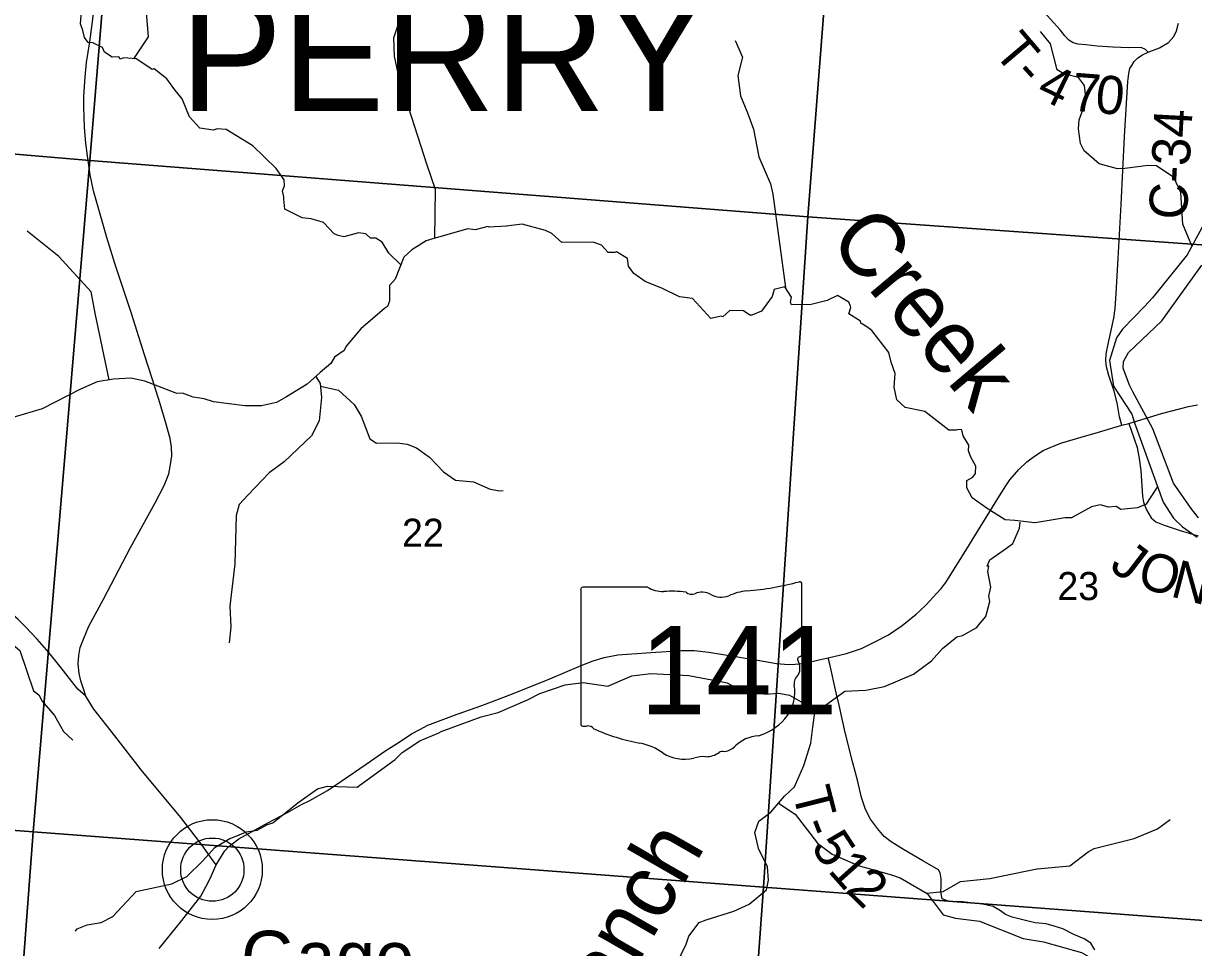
# Model space of a CAD drawing. Extents: x 1878108 to 2183446, y 146837 to 508383.
# Drawn here: x 1996150 to 2005354, y 289361 to 296632 of the extents above; entities that cross this region are included whole.
import ezdxf

# ---------------------------------------------------------------- set-up
doc = ezdxf.new("R2010")
doc.units = 0
for name, color, linetype in [('GM_X_County_Road', 7, 'Continuous'), ('GM_X_County_Road_Text', 7, 'Continuous'), ('GM_X_Major_River', 7, 'Continuous'), ('GM_X_Minor_River', 7, 'Continuous'), ('GM_X_Minor_River_Text', 7, 'Continuous'), ('GM_X_Section', 7, 'Continuous'), ('GM_X_Section_Text', 7, 'Continuous'), ('GM_X_State_Location', 7, 'Continuous'), ('GM_X_State_Route', 7, 'Continuous'), ('GM_X_State_Shield', 7, 'Continuous'), ('GM_X_Township_Road', 7, 'Continuous'), ('GM_X_Township_Road_Text', 7, 'Continuous'), ('GM_X_Township_ROW', 7, 'Continuous'), ('GM_X_Township_Text', 7, 'Continuous'), ('GM_X_Unincorporated', 7, 'Continuous'), ('GM_X_Unincorporated_Location', 7, 'Continuous'), ('GM_X_Unincorporated_Text', 7, 'Continuous')]:
    doc.layers.add(name, color=color, linetype=linetype)

msp = doc.modelspace()

# ---------------------------------------------------------------- linework, layer by layer
at = {"layer": 'GM_X_County_Road'}
for points in [[(2004789, 293470.2), (2004772.2, 293536.3), (2004753, 293648.1), (2004730.1, 293738.3), (2004688, 293862.1), (2004668.8, 293929.4), (2004664, 293978.7), (2004666.4, 294031.6), (2004685.6, 294121.8), (2004726.5, 294314.1), (2004737.3, 294388.7), (2004745.7, 294507.7), (2004760.2, 294783), (2004784.2, 295208.6), (2004811.9, 295743.6), (2004835.9, 296174.1), (2004844.3, 296239), (2004852.7, 296277.5), (2004867.2, 296301.5), (2004887.6, 296332.8), (2004916.5, 296361.6), (2004951.3, 296384.5), (2004997, 296406.1), (2005085.5, 296440.9), (2005157.1, 296482.7), (2005198.8, 296528), (2005220.3, 296573.3), (2005234.6, 296632.9)], [(2004845.5, 293484.6), (2004862.4, 293430.5), (2004909.3, 293294.6), (2004926.1, 293209.3), (2004939.3, 293115.5), (2004952.2, 292913.4), (2004959.8, 292864.1), (2004983.8, 292804.7), (2005020.5, 292741.5), (2005057.1, 292711.2), (2005122.9, 292683.3), (2005249.3, 292642.9), (2005389.6, 292601.2)], [(1996641.8, 291338.4), (1996579.3, 291394.9), (1996436.6, 291574.8), (1996348.9, 291683.3), (1996259.7, 291787.3), (1996167.5, 291885.5), (1996105.1, 291944.9), (1996017.4, 292020.7), (1995889.5, 292127.8), (1995666.5, 292294.3), (1995559.5, 292365.6), (1995456.9, 292423.6), (1995199.8, 292566.3), (1995091.2, 292634.7), (1995063, 292664.4), (1995031.8, 292707.5), (1994993.1, 292802.7), (1994960.4, 292896.3), (1994915.8, 292975.1), (1994884.6, 293013.7)]]:
    msp.add_lwpolyline(points, dxfattribs=at)
at = {"layer": 'GM_X_Major_River'}
for points in [[(2005521.3, 295211.9), (2005304.4, 294812.4), (2005031.4, 294472.9), (2004967.6, 294404.5), (2004794, 294227.6), (2004748.2, 294157.3), (2004692.7, 293980.8), (2004723.3, 293778.6), (2004868, 293558.8), (2004890.2, 293490.8), (2005116, 292866.5), (2005196.4, 292740.6), (2005266.6, 292670.7), (2005382.8, 292591)], [(2005392.4, 292743.3), (2005334.2, 292815.2), (2005195.6, 293015.1), (2005034.3, 293441.2), (2004875.5, 293733.1), (2004849.3, 293787.1), (2004798.9, 293919.1), (2004802.8, 293971.2), (2004842.6, 294043.5), (2005103.9, 294292.8), (2005418.7, 294730.7)]]:
    msp.add_lwpolyline(points, dxfattribs=at)
at = {"layer": 'GM_X_Minor_River'}
for points in [[(1997019, 296353.4), (1997134.7, 296527.8), (1997119.5, 296717.8), (1997097.4, 296805.8), (1996997.1, 297041.8), (1996976.5, 297210.1), (1996933.5, 297345.8), (1996927.1, 297517.1), (1997068.5, 297968), (1997046.2, 298023.8), (1996954.2, 298088.4), (1996898.3, 298152.5), (1996822.2, 298332.6), (1996746.5, 298577.1), (1996696.1, 298691.1)], [(1999387.5, 294943.5), (1999392.6, 295324.3), (1999325.5, 295517.9), (1999105, 296200.5), (1999068.6, 296373.9), (1999064.5, 296518.9), (1999118, 296684.2), (1999215.8, 296822.3), (1999453.7, 297158), (1999598.9, 297254.6), (1999628.7, 297278.8), (1999773.4, 297309.1), (1999947.8, 297391.7), (2000213.7, 297343.4), (2000342.5, 297318.6), (2000496.7, 297340.2), (2000525.2, 297374.5), (2000757.7, 297427), (2000888.3, 297398), (2000974.2, 297420.3), (2001003.2, 297432.4), (2001060, 297470.8), (2001208.8, 297677.8)], [(1999119.7, 294731.6), (1999025.2, 294823.9), (1998972.9, 294909.8), (1998922.8, 294941.8), (1998880.7, 294943.7), (1998842.6, 294975.6), (1998786.5, 294983.5), (1998670.5, 294953.3), (1998626.5, 294963.2), (1998594.4, 294977.1), (1998510.1, 295067), (1998413.9, 295094.8), (1998341.9, 295102.7), (1998207.6, 295170.4), (1998197.3, 295250.4), (1998199.3, 295266.4), (1998189.2, 295314.4), (1998205.1, 295354.4), (1998200.9, 295400.4), (1998138.6, 295490.3), (1997954, 295669.9), (1997745.5, 295797.5), (1997673.4, 295803.4), (1997643.4, 295793.4), (1997537.3, 295807.2), (1997457, 295897), (1997398.5, 296038.9), (1997342.3, 296108.8), (1997278, 296196.7), (1997177.7, 296274.5), (1997163.7, 296270.5), (1997153.7, 296278.4), (1997037.4, 296352.2), (1996939.3, 296362), (1996911.3, 296352), (1996901.2, 296368), (1996847.2, 296365.9), (1996789, 296405.8), (1996772.9, 296441.7), (1996696.8, 296479.6), (1996660.7, 296481.5), (1996630.6, 296521.5), (1996618.4, 296575.5), (1996600.3, 296629.4), (1996615.7, 296829.4)], [(2005339.8, 294881.9), (2005270.5, 295052.1), (2005254, 295301.1), (2005199.5, 295420.2), (2005062.4, 295510.4), (2004996.3, 295515.3), (2004813.4, 295489.7), (2004755.2, 295488.5), (2004611.4, 295526.6), (2004494.5, 295630.5), (2004465.2, 295687.1), (2004448.8, 295801.6), (2004453.8, 295873.8), (2004510.1, 296023.5), (2004495.8, 296144), (2004448.5, 296206.9), (2004396.5, 296219.6), (2004332.6, 296236.5), (2004280.9, 296267.3), (2004227.6, 296470.7), (2004148.8, 296568.1)], [(2001748.9, 296498.9), (2001806.1, 296366.3), (2001770.1, 296222), (2001791.3, 296061.7), (2001846.5, 295929.2), (2001893.9, 295799.3), (2001933.3, 295583.5), (2002027.2, 295370), (2002045.7, 295288.3), (2002143.5, 294554.7)], [(1996825.2, 293828.4), (1996717.7, 294338.3), (1996681.9, 294519.7), (1996429.8, 294798.3), (1996180.3, 294998.2)], [(1999704.2, 295008.9), (1999645.1, 295015), (1999377.1, 294940.6), (1999317.1, 294922.5), (1999205.2, 294850.3), (1999141.3, 294792.1), (1999073.8, 294620), (1999029.9, 294570), (1999030.2, 294448), (1999014.3, 294404), (1998990.4, 294389.9), (1998803.3, 294228.1)], [(1999950.4, 295036.5), (1999813.2, 295029.3), (1999803.2, 295035.3), (1999704.2, 295008.9)], [(2000902, 294782.2), (2000814.5, 294835.2), (2000798.5, 294829.1), (2000748.5, 294829), (2000698.3, 294887), (2000632.2, 294910.8), (2000384, 294908.4), (2000305.7, 294980.2), (2000255.6, 295002.1), (2000073.4, 295051.8), (1999947.1, 295036.4)], [(2004107.5, 292701.9), (2004105, 292703.2), (2003946.9, 292721), (2003872.8, 292726.8), (2003730.4, 292816.6), (2003612.1, 292900.3), (2003569.9, 292978.3), (2003571.7, 293036.3), (2003617.6, 293062.3), (2003637.6, 293090.4), (2003641.4, 293148.4), (2003603.2, 293220.3), (2003583, 293268.3), (2003586.9, 293314.3), (2003540.7, 293386.2), (2003530.5, 293434.2), (2003504.5, 293438.1), (2003486.5, 293432.1), (2003428.5, 293432), (2003239.9, 293579.6), (2003085.7, 293611.4), (2003019.5, 293671.2), (2002999.2, 293771.2), (2003006.9, 293877.2), (2002974.6, 293967.1), (2002958.4, 294043.1), (2002823.8, 294214.8), (2002783.7, 294244.8), (2002735.6, 294274.7), (2002735.5, 294290.7), (2002643.3, 294346.5), (2002657.2, 294396.5), (2002655.2, 294408.5), (2002643.1, 294438.5), (2002552.8, 294492.3), (2002472.9, 294452.2), (2002334.9, 294417.9), (2002214.8, 294419.7), (2002192.8, 294417.7), (2002182.7, 294439.7), (2002192.6, 294477.7), (2002140.3, 294559.6), (2002054.3, 294539.4), (2002040.5, 294483.4), (2001954.7, 294369.3), (2001880.8, 294337.1), (2001862.7, 294337.1), (2001814.6, 294371), (2001706.5, 294372.8), (2001650.6, 294322.7), (2001638.6, 294328.7), (2001556.6, 294310.5), (2001414, 294468.3), (2001311.9, 294480.1), (2001177.6, 294545.8), (2001041.4, 294601.6), (2000951.1, 294663.4), (2000908.9, 294721.3), (2000902, 294782.2)], [(1998803.3, 294228.1), (1998688.9, 294091.4), (1998673, 294059.4), (1998597.1, 294005.2), (1998569.2, 293955.2), (1998483.4, 293885), (1998381.5, 293794.9), (1998219.7, 293694.6), (1998139.7, 293648.4), (1998023.7, 293624.2)], [(1998023.7, 293624.2), (1997891.6, 293622), (1997645.3, 293653.5), (1997573.2, 293679.4), (1997485.1, 293691.2), (1997401, 293723.1), (1997356.9, 293721), (1997342.9, 293725), (1997104.5, 293816.5), (1996996.3, 293840.3), (1996858.2, 293834.1), (1996730.2, 293811.9), (1996600.3, 293755.6), (1996298.5, 293599.1), (1996014.5, 293514.6)], [(1998449.4, 293855), (1998484.6, 293797.7), (1998495.2, 293688.4), (1998476.6, 293504.7), (1998416.3, 293386.1), (1998201.4, 293181.6), (1998083.2, 293097.1), (1997918.6, 292923.4), (1997847.1, 292847.8), (1997823.1, 292761), (1997813.1, 292379.6), (1997774.3, 292046.5), (1997781.3, 291885.1), (1997768.5, 291757.3)], [(1998486.7, 293776.9), (1998627.7, 293745.7), (1998752.6, 293632.7), (1998806.7, 293542.5), (1998874.9, 293364.9), (1998926.7, 293329.2), (1999089.6, 293332.2), (1999169.3, 293322.8), (1999241.6, 293293.7), (1999344.9, 293218.3), (1999455.6, 293104.2), (1999549.5, 293037.5), (1999689.3, 293025.9), (1999821.9, 292966.6), (1999897.3, 292953.5), (1999923.7, 292957.7)], [(2005071.7, 292990.1), (2005002.2, 292882.6), (2004980.6, 292850.3), (2004912.8, 292821.7), (2004780.7, 292808.5), (2004746.3, 292830.2), (2004684.2, 292825.7), (2004619.9, 292843.1), (2004551.9, 292828.5), (2004392.7, 292742.9), (2004344.6, 292742.5), (2004107.5, 292701.9)], [(1996560.6, 289490.6), (1996572, 289507.7), (1996652, 289539.9), (1996762, 289558.1), (1996853.9, 289606.2), (1997001.6, 289762.5), (1997037.5, 289802.6), (1997317.6, 289861.1), (1997435.5, 289919.3), (1997559.3, 290041.5), (1997655.1, 290147.7), (1997772.9, 290219.9), (1997789, 290223.9), (1997904.9, 290272.1), (1997988.9, 290284.3), (1998068.9, 290328.4), (1998110.9, 290342.5), (1998308.6, 290498.9), (1998462.4, 290611.1), (1998542.4, 290631.3), (1998774.6, 290623.7), (1998796.6, 290637.8), (1999074.3, 290840.2), (1999128.1, 290896.3), (1999268, 290986.6), (1999417.9, 291050.9), (1999435.9, 291060.9), (1999749.9, 291175.5), (1999883.9, 291211.7), (2000115.8, 291310.1), (2000211.7, 291360.3), (2000411.7, 291428.7), (2000551.7, 291446.9), (2000748, 291417.3), (2000935.9, 291499.6), (2001086, 291517.9), (2001384.2, 291502.4), (2001620.5, 291456.8), (2001686.6, 291445), (2001768.8, 291397.1), (2001855, 291375.2), (2001917, 291369.4), (2001985.1, 291355.5), (2002093.2, 291363.7), (2002175.3, 291345.8), (2002339.7, 291252.1), (2002393.7, 291248.2), (2002429.8, 291248.3), (2002611.5, 291378.6), (2002775.6, 291386.9), (2002923.7, 291415.2), (2003151.6, 291511.6), (2003293.4, 291617.8), (2003379.2, 291714), (2003491, 291806.2), (2003537, 291816.3), (2003649, 291880.5), (2003662.9, 291896.5), (2003720.8, 291964.6), (2003750.5, 292082.6), (2003744.3, 292126.6), (2003758.2, 292196.6), (2003735.8, 292318.6), (2003743.7, 292362.6), (2003731.7, 292360.6), (2003751.6, 292412.6), (2003881.4, 292502.8), (2003933.4, 292538.9), (2003985.1, 292661), (2003988.9, 292709)], [(1995565.1, 292003), (1995745.8, 291993.6), (1995806.3, 291967.4), (1995979.7, 291800.7), (1996016.8, 291786.1), (1996121.3, 291698.6), (1996230.2, 291381.5), (1996270.3, 291350.6)], [(1996270.3, 291350.6), (1996296.9, 291298.5), (1996393.7, 291187.4), (1996465.5, 291061.8), (1996539.1, 290992.5)], [(2001206.8, 289062.1), (2001362.1, 289388.3), (2001383.9, 289450.4), (2001465.7, 289558.5), (2001519.7, 289578.6), (2001737.6, 289647), (2001857.6, 289703.2), (2001995.4, 289815.5), (2002011.2, 289891.5), (2002002.9, 289995.5), (2001932.4, 290141.4), (2001930.4, 290153.4), (2001902.1, 290265.3), (2001933.8, 290355.4), (2002029.7, 290425.6), (2002137.5, 290551.8), (2002215.3, 290625.9), (2002288.9, 290794), (2002344.5, 290968.1), (2002360.1, 291094.2), (2002379.1, 291249.3)], [(2002090.5, 290496.7), (2002220.3, 290410.3), (2002395.4, 290181.2), (2002512, 290094.8), (2002716.9, 290006.4), (2002979, 289932.3), (2003045.8, 289909.6), (2003258.3, 289786.5), (2003383.3, 289617.2), (2003482.1, 289592.3), (2003671.2, 289567.4), (2004013.6, 289433.4), (2004174.4, 289406.4)], [(2004123.4, 289980.4), (2004381.1, 290004.2), (2004525.3, 290114.8), (2004571.3, 290140.9), (2004887.6, 290219.5), (2005069.8, 290296), (2005169.9, 290368.4)], [(2003255.9, 289787.9), (2003383.9, 289802.1), (2003521.9, 289881.2), (2003750.4, 289903.8), (2004133.7, 289982.5)], [(2004174.4, 289406.4), (2004473, 289321.8), (2004605, 289245.6), (2004761.1, 289193.6), (2004855.2, 289109.4), (2004887.2, 288989), (2004957.2, 288876.6), (2004997.2, 288772.3), (2005073.1, 288344.8), (2005065, 288152), (2005105, 288055.7)]]:
    msp.add_lwpolyline(points, dxfattribs=at)
at = {"layer": 'GM_X_Section'}
for points in [[(1997112.9, 300922.7), (1996672.7, 295553.3), (1991165.2, 296023.3), (1991629.4, 301366.7)], [(2002740.4, 300502.8), (2002320.3, 295109.3), (1996672.7, 295553.3), (1997112.9, 300922.7)], [(2008238.6, 300131.7), (2007847.8, 294715.6), (2002320.3, 295109.3), (2002740.4, 300502.8)], [(1996672.7, 295553.3), (1996226.4, 290271.9), (1990757, 290692), (1991165.2, 296023.3)], [(2002320.3, 295109.3), (2001970, 289836), (1996226.4, 290271.9), (1996672.7, 295553.3)], [(2002320.3, 295109.3), (2007847.8, 294715.6), (2007476.8, 289419.7), (2001970, 289836)], [(1996226.4, 290271.9), (1995818.2, 284842.4), (1990274.7, 285348.5), (1990757, 290692)], [(2001970, 289836), (2001581.8, 284434.5), (1995818.2, 284842.4), (1996226.4, 290271.9)], [(2001970, 289836), (2007476.8, 289419.7), (2007099.8, 284117.7), (2001581.8, 284434.5)]]:
    msp.add_lwpolyline(points, close=True, dxfattribs=at)
at = {"layer": 'GM_X_State_Route'}
for points in [[(1997666.8, 290011.2), (1997642.8, 290042.5), (1997553.8, 290169.9), (1997387.9, 290383.9), (1997077.7, 290760.2), (1996870.6, 291026.2), (1996704.1, 291237.3), (1996641.8, 291338.4), (1996621.8, 291395.5), (1996601.8, 291459.9), (1996587.5, 291518.5), (1996581.8, 291592.8), (1996586.1, 291658.5), (1996596.1, 291721.4), (1996621.8, 291788.6), (1996666.1, 291890), (1996779, 292103), (1996992.7, 292508.9), (1997186.3, 292859), (1997256.6, 292996.4), (1997294.9, 293089.1), (1997307.8, 293160.5), (1997317.8, 293229.1), (1997316.3, 293300.6), (1997304.9, 293366.3), (1997273.5, 293479.2), (1997226.3, 293637.8), (1997166.3, 293829.3), (1997102, 294025.1), (1996999.1, 294351), (1996870.5, 294744), (1996807.6, 294946.9), (1996737.5, 295185.6), (1996700.4, 295314.2), (1996674.7, 295440), (1996653.2, 295591.5), (1996640.4, 295688.6), (1996630.4, 295813), (1996628.9, 295895.9), (1996626.1, 295970.2), (1996626.1, 296057.3), (1996636.1, 296213.1), (1996646.1, 296324.6), (1996671.8, 296487.5), (1996734.7, 296966.3)], [(2004845.5, 293484.6), (2005101.6, 293561.7), (2005314.6, 293617.5), (2005384.7, 293630.3)], [(2003200.4, 292010.4), (2003251.3, 292057.5), (2003333.1, 292147.7), (2003367.9, 292187.3), (2003405.2, 292234.2), (2003569.9, 292498.7), (2003815.2, 292894.3), (2003876.5, 292992.9), (2003909.7, 293040.8), (2003978.7, 293121.5), (2004042.4, 293181.6), (2004102.5, 293227.3), (2004171.1, 293270.6), (2004243.2, 293303), (2004318.4, 293331.3), (2004469.2, 293377.6), (2004605.1, 293416.1), (2004789, 293470.2), (2004845.5, 293484.6)], [(1997666.8, 290011.2), (1997708.9, 290079.8), (1997735.3, 290123), (1997765.4, 290156.7), (1997799, 290183.2), (1997843.5, 290216.8), (1998078, 290344.3), (1998227.1, 290424.8), (1998336.5, 290486.1), (1998402.6, 290517.4), (1998542, 290597.9), (1998653.9, 290673.7), (1998847.4, 290803.5), (1999001.3, 290911.7), (1999105.9, 290977.9), (1999203.3, 291041.6), (1999267, 291077.6), (1999331.9, 291111.3), (1999562.8, 291198.6), (1999756.3, 291266.4), (1999998, 291356.6), (2000290.1, 291474.4), (2000536.6, 291580.2), (2000631.6, 291617.5), (2000718.2, 291643.9), (2000825.2, 291663.2), (2001086, 291683.6), (2001326.5, 291699.2), (2001426.3, 291699.2), (2001541.7, 291686), (2001895.2, 291627.1), (2002073.1, 291595.8), (2002166.9, 291587.4), (2002221, 291589.8), (2002297.9, 291598.2), (2002406.1, 291623.5), (2002480.7, 291640.3), (2002623.7, 291675.2), (2002741.6, 291714.8), (2002847.4, 291765.3), (2002954.4, 291821.8), (2003062.6, 291895.2), (2003170.8, 291983), (2003200.4, 292010.4)], [(1997217.2, 289353.6), (1997395.1, 289574.8), (1997545.4, 289764.8), (1997588.7, 289844.1), (1997619.9, 289905.4), (1997666.8, 290011.2)]]:
    msp.add_lwpolyline(points, dxfattribs=at)
at = {"layer": 'GM_X_State_Shield'}
for p, q in [((2000533.3, 292177.6), (2000533.3, 291121)), ((2001060.1, 292195.8), (2000550.4, 292195.8)), ((2002273.5, 291669.2), (2002273.5, 292222)), ((2002273.3, 291669.4), (2002273.5, 291669.2))]:
    msp.add_line(p, q, dxfattribs=at)
for centre, major_axis, start_param, end_param in [((2001653.6, 293636.3), (1845.5, 0), 4.814394, 5.042369), ((2002254.2, 292224.3), (19.4, 0), 6.141152, 7.989035), ((2000553.2, 292179.9), (20.2, 0), 1.712693, 3.28349), ((2001181.4, 292318.4), (195.5, 0), 4.042523, 4.731795), ((2001246.3, 291602.6), (702, 0), 1.404758, 1.657858), ((2001405.6, 292185.3), (56.4, 0), 3.836095, 5.185415), ((2001488.5, 292063.2), (117.3, 0), 0.950623, 2.079405), ((2001639.8, 292230.7), (141.1, 0), 4.081561, 5.145723), ((2001889, 291873.1), (371.3, 0), 1.699011, 2.107814), ((2002269, 291628.7), (30, 0), 1.883978, 3.671073), ((2002078.3, 291558.8), (180, 0), 5.934695, 6.695948), ((2002252.8, 291667.1), (20.7, 0), 5.05454, 6.418171), ((2002342.9, 291437.9), (130.9, 0), 2.387724, 3.262537), ((2001757, 291367.6), (461.6, 0), 5.101752, 6.440018), ((2000553.4, 291118.7), (20.3, 0), 3.00124, 4.508301), ((2000556.5, 291226.8), (155.2, 0), 4.665946, 4.897461), ((2000588.3, 291060), (56, 0), 0.519207, 1.627899), ((2001294.9, 292009.4), (1332.7, 0), 4.195997, 4.488961), ((2000897.5, 290646.3), (417, 0), 0.823519, 1.323587), ((2001631.3, 291018.6), (149.1, 0), 4.937069, 5.64225), ((2001951.6, 290824.3), (252.8, 0), 1.647645, 2.488434), ((2001348.5, 291054.8), (264.6, 0), 4.026481, 4.996735), ((2001501.4, 290689.4), (217.4, 0), 1.495662, 1.94098), ((2001520.7, 290975.6), (141, 0), 4.691044, 5.507374), ((2001648.3, 290873.3), (39.7, 0), 1.147584, 2.315152)]:
    msp.add_ellipse(centre, major_axis=major_axis, ratio=0.8, start_param=start_param, end_param=end_param, dxfattribs=at)
at = {"layer": 'GM_X_Township_Road'}
for points in [[(2004997, 296406.1), (2004977, 296427.8), (2004942.4, 296442.1), (2004845.8, 296439.7), (2004718.2, 296444.5), (2004596, 296453.7), (2004505.9, 296463.6), (2004445.1, 296469.5), (2004405.7, 296479.1), (2004372.3, 296500.6), (2004341.3, 296533.9), (2004304.3, 296580.5), (2004152.8, 296749.8), (2004003.8, 296915.6), (2003906, 297017), (2003871.4, 297050.4), (2003832, 297083.8), (2003786.7, 297102.9), (2003734.2, 297119.6), (2003696, 297123.1), (2003613.7, 297120.8), (2003563.6, 297124.3), (2003488.5, 297130.3), (2003374.4, 297140.4)], [(2003672.3, 289704.7), (2003638.1, 289708.4), (2003535.7, 289720.9), (2003431.3, 289723.9), (2003376.5, 289743.9), (2003366, 289798.3), (2003368.5, 289840.7), (2003368.5, 289901.8), (2003361, 289949.3), (2003347.3, 289971.7), (2003223.7, 290043), (2003071.5, 290132.7), (2002975.4, 290192.6), (2002919.3, 290233.8), (2002866.9, 290297.4), (2002813.2, 290371.1), (2002773.3, 290448.4), (2002742.1, 290542), (2002709.6, 290676.8), (2002674.7, 290814.1), (2002614.8, 291052.4), (2002567.4, 291267.1), (2002542, 291366.2), (2002493.9, 291589.8), (2002480.7, 291640.3)]]:
    msp.add_lwpolyline(points, dxfattribs=at)
at = {"layer": 'GM_X_Township_ROW'}
msp.add_lwpolyline([(2004577.7, 289344), (2004546.5, 289395.2), (2004492.9, 289428.9), (2004411.8, 289462.6), (2004324.4, 289507.5), (2004258.3, 289530), (2004193.4, 289547.4), (2004106.9, 289555.8), (2004063.6, 289566.2), (2003927.6, 289601.1), (2003873.9, 289621.1), (2003835.2, 289649.8), (2003776.6, 289683.5), (2003706.7, 289700.9), (2003672.3, 289704.7)], dxfattribs=at)
at = {"layer": 'GM_X_Unincorporated'}
for radius in [392.8, 249]:
    msp.add_circle((1997636.2, 289974), radius, dxfattribs=at)
at = {"layer": 'GM_X_Unincorporated_Location'}
msp.add_line((1997636.2, 289974), (1997636.2, 289974), dxfattribs=at)

# ---------------------------------------------------------------- texts
at = {"layer": 'GM_X_County_Road_Text'}
for s, rotation, p in [('C-34', 86.96345, (2005300.2, 295082.7)), ('J', 322.61715, (2004682.5, 292345.6)), ('O', 342.93833, (2004897.1, 292207.2)), ('N', 345.38652, (2005163, 292126))]:
    msp.add_text(s, height=300, rotation=rotation, dxfattribs=at).set_placement(p)
at = {"layer": 'GM_X_Minor_River_Text'}
for s, height, rotation, p in [('Creek', 499.97, 310.10831, (2002473.2, 294920)), ('Branch', 499.99, 60.10337, (2000460.5, 288318.7))]:
    msp.add_text(s, height=height, rotation=rotation, dxfattribs=at).set_placement(p)
at = {"layer": 'GM_X_Section_Text'}
for s, p in [('22', (1999127.8, 292514.3)), ('23', (2004282.4, 292094.7))]:
    msp.add_text(s, height=221, rotation=0.00001, dxfattribs=at).set_placement(p)
at = {"layer": 'GM_X_State_Location'}
msp.add_text('141', height=1, rotation=0.00001, dxfattribs=at).set_placement((2001030.8, 291506.3))
for s in ['s', 'r']:
    msp.add_text(s, height=1, dxfattribs=at).set_placement((2001383.8, 291579))
at = {"layer": 'GM_X_State_Shield'}
msp.add_text('141', height=696.1, dxfattribs=at).set_placement((2001000.7, 291195.5))
at = {"layer": 'GM_X_Township_Road_Text'}
for s, rotation, p in [('T', 310.28405, (2003771.6, 296404)), ('-', 312.25552, (2003924.2, 296224.3)), ('4', 333.94704, (2004105.4, 296059.2)), ('7', 355.56592, (2004389.8, 295945.8)), ('0', 353.93134, (2004571.8, 295931.7)), ('T', 284.15578, (2002196.4, 290587.3)), ('-', 291.0718, (2002263.2, 290332.1)), ('5', 303.3359, (2002339.5, 290155)), ('1', 311.72745, (2002470.2, 289962.6)), ('2', 315.79296, (2002609.2, 289807.9))]:
    msp.add_text(s, height=300, rotation=rotation, dxfattribs=at).set_placement(p)
at = {"layer": 'GM_X_Township_Text'}
msp.add_text('PERRY', height=900, rotation=0.00001, dxfattribs=at).set_placement((1997383.4, 295942))
at = {"layer": 'GM_X_Unincorporated_Text'}
msp.add_text('Gage', height=417, rotation=0.00001, dxfattribs=at).set_placement((1997862.8, 289075.8))

doc.saveas('drawing.dxf')
